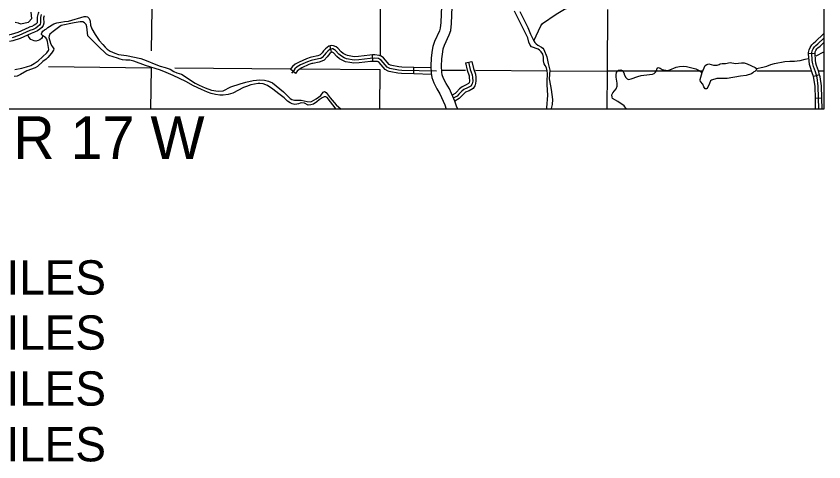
# Model space of a CAD drawing. Extents: x 1373862 to 1376999, y 1168398 to 1170455.
# Drawn here: x 1375806.5 to 1376182.8, y 1168398.5 to 1168606.3 of the extents above; entities that cross this region are included whole.
import ezdxf

# ---------------------------------------------------------------- set-up
doc = ezdxf.new("R2010")
doc.units = 0
for name, color, linetype in [('Level 10', 7, 'Continuous'), ('Level 32', 7, 'Continuous'), ('Level 35', 7, 'Continuous'), ('Level 45', 7, 'Continuous'), ('Level 5', 7, 'Continuous'), ('R_Draft', 7, 'Continuous')]:
    doc.layers.add(name, color=color, linetype=linetype)

msp = doc.modelspace()

# ---------------------------------------------------------------- linework, layer by layer
at = {"layer": 'Level 10'}
for points in [[(1376004.64, 1168610.93), (1376004.32, 1168603.27), (1376004.04, 1168600.69), (1376003.62, 1168599.45), (1376001.3, 1168594.52), (1376000.59, 1168592.17), (1376000.25, 1168590.43), (1375999.83, 1168586.77), (1375999.7, 1168582.99), (1375999.84, 1168579.72), (1376000.12, 1168577.72), (1376001.01, 1168575.19), (1376002.44, 1168572.4), (1376003.84, 1168570.04), (1376006.15, 1168564.87), (1376006.74, 1168562.99)], [(1376012.17, 1168562.99), (1376011.58, 1168564.28), (1376010.83, 1168566.65), (1376008.29, 1168572.34), (1376006.82, 1168574.82), (1376005.61, 1168577.17), (1376005, 1168578.9), (1376004.82, 1168580.17), (1376004.7, 1168583.01), (1376004.82, 1168586.39), (1376005.19, 1168589.66), (1376005.45, 1168590.97), (1376005.98, 1168592.72), (1376008.27, 1168597.58), (1376008.96, 1168599.63), (1376009.3, 1168602.9), (1376009.64, 1168610.64)]]:
    msp.add_lwpolyline(points, dxfattribs=at)
at = {"layer": 'Level 32'}
for p, q in [((1376182.76, 1168597.59), (1376182.47, 1168597.89)), ((1376178.67, 1168588.83), (1376175.67, 1168588.67)), ((1376180.76, 1168578.89), (1376177.87, 1168578.07)), ((1376181.8, 1168568.05), (1376178.8, 1168567.96))]:
    msp.add_line(p, q, dxfattribs=at)
for points in [[(1376175.67, 1168588.67), (1376175.64, 1168589.26), (1376175.92, 1168590.54), (1376176.38, 1168591.67), (1376177.12, 1168592.87), (1376177.96, 1168593.74), (1376179.03, 1168594.57), (1376182.47, 1168597.89)], [(1376180.47, 1168562.99), (1376180.16, 1168573.6), (1376179.58, 1168577.67), (1376178.81, 1168580.37), (1376177.94, 1168582.78), (1376177.62, 1168583.98), (1376177.37, 1168585.54), (1376177.18, 1168589.14), (1376177.38, 1168590.08), (1376177.75, 1168590.97), (1376178.33, 1168591.93), (1376178.98, 1168592.6), (1376180.03, 1168593.42), (1376182.76, 1168596.05)], [(1376182.47, 1168597.89), (1376182.56, 1168597.98), (1376182.76, 1168598.24)], [(1376178.67, 1168588.83), (1376178.66, 1168589.02), (1376178.79, 1168589.64), (1376179.06, 1168590.3), (1376179.5, 1168591.02), (1376179.97, 1168591.5), (1376181, 1168592.31), (1376182.76, 1168594)], [(1376177.87, 1168578.07), (1376177.36, 1168579.9), (1376176.48, 1168582.32), (1376176.12, 1168583.67), (1376175.85, 1168585.38), (1376175.67, 1168588.67)], [(1376180.76, 1168578.89), (1376180.22, 1168580.82), (1376179.34, 1168583.22), (1376179.06, 1168584.29), (1376178.84, 1168585.7), (1376178.67, 1168588.83)], [(1376178.8, 1168567.96), (1376178.64, 1168573.47), (1376178.08, 1168577.35), (1376177.87, 1168578.07)], [(1376181.8, 1168568.05), (1376181.63, 1168573.73), (1376181.02, 1168577.97), (1376180.76, 1168578.89)], [(1376178.94, 1168562.99), (1376178.8, 1168567.96)], [(1376181.95, 1168562.99), (1376181.8, 1168568.05)]]:
    msp.add_lwpolyline(points, dxfattribs=at)
at = {"layer": 'Level 35'}
for points in [[(1376047.64, 1168594.74), (1376050.83, 1168601.79), (1376051.65, 1168602.88), (1376058.05, 1168607.27), (1376061.92, 1168609.53), (1376064.44, 1168610.39), (1376066.44, 1168610.78), (1376072.96, 1168610.95), (1376075.51, 1168611.11), (1376076.3, 1168611.03), (1376080.45, 1168610.95)], [(1375805.8, 1168581.38), (1375809.04, 1168582.07), (1375811.22, 1168582.65), (1375813.31, 1168583.32), (1375814.85, 1168584.17), (1375816.78, 1168585.5), (1375820.7, 1168589.1), (1375821.54, 1168590.23), (1375821.65, 1168590.71), (1375821.11, 1168594.42), (1375820.75, 1168595.48), (1375820.34, 1168596.17), (1375818.69, 1168597.22), (1375818.33, 1168597.71), (1375818.24, 1168598.03), (1375818.39, 1168598.57), (1375818.86, 1168599.26), (1375819.61, 1168599.83), (1375820.52, 1168600.29), (1375821.28, 1168601.04), (1375823.94, 1168602.7), (1375825.43, 1168603.21), (1375827.24, 1168603.54), (1375829.03, 1168603.81), (1375830.92, 1168603.94), (1375838.15, 1168606.08), (1375839.05, 1168606.07), (1375839.71, 1168605.92), (1375840.48, 1168605.12), (1375840.92, 1168603.96), (1375841.11, 1168602.13), (1375841.72, 1168600.42), (1375843.22, 1168597.65), (1375845.2, 1168594.92), (1375846.78, 1168593.13)], [(1375812.21, 1168603.46), (1375813.81, 1168605.26), (1375813.51, 1168608.06)], [(1376053.56, 1168562.99), (1376053.76, 1168563.47), (1376054.12, 1168569.39), (1376053.86, 1168574.24), (1376053.83, 1168575.88), (1376053.97, 1168579.5), (1376053.91, 1168580.74), (1376053.49, 1168582.23), (1376052.95, 1168583.34), (1376052.48, 1168584.03), (1376052.12, 1168585.4), (1376052.15, 1168587.14), (1376051.77, 1168588.48), (1376051.03, 1168589.66), (1376050.32, 1168590.41), (1376049.6, 1168590.88), (1376046.57, 1168592.03), (1376045.98, 1168592.72), (1376045.36, 1168594.19), (1376044.89, 1168596.24), (1376038.58, 1168608.54)], [(1376041.11, 1168608.49), (1376044.79, 1168601.03), (1376046.09, 1168597.86), (1376047.64, 1168594.74), (1376048.15, 1168593.99), (1376048.76, 1168593.38), (1376049.57, 1168592.74), (1376051.22, 1168591.8), (1376051.76, 1168591.39), (1376052.27, 1168590.78), (1376053.74, 1168587.25), (1376054.29, 1168584.16), (1376054.99, 1168581.77), (1376055.04, 1168581.03), (1376054.85, 1168577.13), (1376054.9, 1168576.28), (1376055.73, 1168572.03), (1376056.35, 1168567.35), (1376056.18, 1168565.08), (1376055.78, 1168563.16), (1376055.71, 1168562.99)], [(1375833.5, 1168603.12), (1375827.42, 1168601.86), (1375823.68, 1168599.14), (1375822.17, 1168597.86), (1375821.78, 1168597.17), (1375821.74, 1168596.33), (1375822.5, 1168593.61), (1375822.97, 1168592.59), (1375823.44, 1168591.96), (1375823.96, 1168591.03), (1375823.91, 1168590.37), (1375822.91, 1168589.02), (1375821.25, 1168587.07), (1375820.45, 1168586.28), (1375818.91, 1168585.11), (1375816.38, 1168582.73), (1375815.34, 1168582.16), (1375811.47, 1168580.75), (1375808.55, 1168579.01), (1375806.95, 1168578.3), (1375805.58, 1168578.16)], [(1375805.99, 1168603.55), (1375807.37, 1168603.18), (1375808.48, 1168602.64)], [(1375808.48, 1168602.64), (1375812.21, 1168603.46)], [(1375955.55, 1168562.99), (1375953.92, 1168564.88), (1375952.88, 1168566.38), (1375951.37, 1168568.29), (1375950.75, 1168568.68), (1375949.93, 1168568.63), (1375949.08, 1168568.21), (1375947.7, 1168567.33), (1375946.5, 1168566.31), (1375945.03, 1168565.29), (1375943.76, 1168564.87), (1375942.48, 1168564.83), (1375940.79, 1168565.7), (1375939.48, 1168565.92), (1375938.78, 1168565.76), (1375938.03, 1168565.43), (1375937.29, 1168565.24), (1375936.22, 1168565.16), (1375935, 1168565.44), (1375934.04, 1168565.83), (1375932.93, 1168566.61), (1375931.29, 1168568.12), (1375928.91, 1168570.02), (1375926.08, 1168572.17), (1375923.5, 1168573.89), (1375921.49, 1168574.69), (1375919.98, 1168574.89), (1375919.28, 1168574.86), (1375915.86, 1168574.2), (1375913.72, 1168573.53), (1375912.4, 1168572.98), (1375907.36, 1168570.38), (1375905.2, 1168569.71), (1375902.95, 1168569.43), (1375901.3, 1168569.46), (1375899.34, 1168569.73), (1375897.38, 1168570.28), (1375895.53, 1168570.91), (1375892.84, 1168572.02), (1375889.09, 1168573.8), (1375885.45, 1168575.76), (1375879.58, 1168578.64), (1375876.37, 1168580.02), (1375873.78, 1168581.02), (1375866.67, 1168583.28), (1375861.34, 1168585.27), (1375859.44, 1168585.7), (1375857.62, 1168585.75), (1375855.95, 1168585.94), (1375854.89, 1168586.19), (1375853.62, 1168586.72), (1375849.56, 1168587.86), (1375848.59, 1168588.6), (1375844.48, 1168592.39), (1375839.92, 1168597.11), (1375839.37, 1168601.32), (1375839.07, 1168602.35), (1375838.36, 1168603.2), (1375837.56, 1168603.61), (1375836.34, 1168603.69), (1375833.5, 1168603.12)], [(1375818.69, 1168597.22), (1375818.51, 1168596.26), (1375818.28, 1168595.85), (1375817.51, 1168595.16), (1375816.74, 1168594.87), (1375815.61, 1168594.65), (1375814.83, 1168594.8), (1375813.32, 1168595.39), (1375812.33, 1168596.46), (1375812.06, 1168597.19), (1375812.01, 1168597.54)], [(1375846.78, 1168593.13), (1375847.98, 1168591.75), (1375848.83, 1168590.96), (1375850.2, 1168589.99), (1375852.39, 1168588.98), (1375854.09, 1168588.47), (1375857.81, 1168587.95), (1375864.53, 1168586.46), (1375867.05, 1168585.61), (1375871.55, 1168583.66), (1375873.53, 1168582.96), (1375875.81, 1168582.41), (1375878.28, 1168581.56), (1375879.95, 1168580.5), (1375881.35, 1168579.85), (1375883.54, 1168579.2), (1375889.86, 1168575.11), (1375891.69, 1168574.1), (1375894.5, 1168572.83), (1375897.53, 1168571.84), (1375900.51, 1168571.35), (1375902.96, 1168571.49), (1375906.51, 1168573.29), (1375910.89, 1168574.78), (1375913.41, 1168575.5), (1375916.94, 1168576.28), (1375920.03, 1168576.61), (1375922.2, 1168576.42), (1375923.96, 1168575.93), (1375925.81, 1168575.18), (1375930.96, 1168570.97), (1375934.1, 1168567.89), (1375934.93, 1168567.38), (1375936.17, 1168567.04), (1375938.26, 1168567.16), (1375939.3, 1168567.09), (1375942.06, 1168566.42), (1375943.45, 1168566.32), (1375944.13, 1168566.53), (1375946.28, 1168567.71), (1375948.39, 1168569.36), (1375949.48, 1168570.9), (1375950.17, 1168571.13), (1375950.88, 1168570.64), (1375952.75, 1168568.15), (1375955.55, 1168564.96), (1375957.95, 1168562.99)], [(1376179.15, 1168587.83), (1376182.76, 1168589.71)], [(1376126.06, 1168580.07), (1376127.44, 1168583.29), (1376128.17, 1168583.72), (1376129.12, 1168584), (1376131.28, 1168583.41), (1376133.06, 1168583.46), (1376133.97, 1168583.76), (1376134.48, 1168584.04), (1376135.45, 1168584.28), (1376136.91, 1168584.26), (1376139.11, 1168584.68), (1376141.67, 1168584.28), (1376144.44, 1168584.59), (1376145.59, 1168584.59), (1376147.08, 1168584.05), (1376150.77, 1168582.34), (1376151.4, 1168581.89), (1376151.44, 1168581.63), (1376151.19, 1168581.08), (1376150.66, 1168580.51), (1376150.17, 1168580.25), (1376149.6, 1168579.78), (1376149.03, 1168579.45), (1376146.63, 1168578.61), (1376143.94, 1168578.34), (1376137.68, 1168577.28), (1376132.92, 1168577.14), (1376130.38, 1168576.5), (1376129.95, 1168576.08), (1376129.53, 1168574.81), (1376128.38, 1168572.59), (1376128.1, 1168572.43), (1376127.46, 1168572.32), (1376126.87, 1168573.31), (1376126.35, 1168574.5), (1376125.31, 1168575.76), (1376125.1, 1168576.44), (1376125.06, 1168576.73), (1376126.06, 1168580.07)], [(1376151.4, 1168581.89), (1376154.3, 1168582.47), (1376156.24, 1168583.02), (1376158.1, 1168583.76), (1376159.81, 1168584.26), (1376164.52, 1168585.08), (1376166.88, 1168585.34), (1376169.07, 1168585.32), (1376170.33, 1168585.42), (1376171.8, 1168585.64), (1376174.06, 1168586.28), (1376175.47, 1168586.5)], [(1376090.84, 1168562.99), (1376089.67, 1168564.4), (1376086.81, 1168566.47), (1376084.35, 1168567.91), (1376084.07, 1168568.48), (1376084.03, 1168569.56), (1376084.45, 1168570.55), (1376085.97, 1168572.45), (1376086.49, 1168573.64), (1376086.51, 1168575.06), (1376086.02, 1168577.83), (1376086.04, 1168578.93), (1376086.23, 1168579.95), (1376086.65, 1168580.66), (1376087.16, 1168581.13), (1376088.22, 1168581.26), (1376088.9, 1168580.97), (1376089.58, 1168579.87), (1376089.93, 1168578.77), (1376090.43, 1168577.74), (1376091.08, 1168577.01), (1376091.76, 1168576.78), (1376092.97, 1168577), (1376096.08, 1168578.17), (1376097.59, 1168578.6), (1376098.9, 1168578.84), (1376102.88, 1168579.29), (1376103.63, 1168579.52), (1376104.28, 1168580.17), (1376104.78, 1168580.94), (1376105.18, 1168582), (1376105.56, 1168582.33), (1376106.5, 1168582), (1376107.5, 1168581.46)], [(1376107.5, 1168581.46), (1376109.88, 1168580.92), (1376111.07, 1168581.28), (1376113.98, 1168582.47), (1376115.51, 1168582.81), (1376117.18, 1168582.94), (1376118.78, 1168582.85), (1376123.14, 1168581.7), (1376124.41, 1168581.1), (1376126.06, 1168580.07)]]:
    msp.add_lwpolyline(points, dxfattribs=at)
at = {"layer": 'Level 45'}
for p, q in [((1375953.41, 1168589.47), (1375952.8, 1168592.41)), ((1375972.6, 1168585.17), (1375972.52, 1168588.17)), ((1376015.8, 1168584.47), (1376018.72, 1168585.15)), ((1375936.53, 1168579.6), (1375934.3, 1168581.6)), ((1375991.71, 1168579.35), (1375991.78, 1168582.35))]:
    msp.add_line(p, q, dxfattribs=at)
for points in [[(1375818.11, 1168607.02), (1375817.74, 1168605.62), (1375817.84, 1168603.18), (1375817.69, 1168602.52), (1375817.34, 1168602.06), (1375816.61, 1168601.4), (1375815.59, 1168600.69), (1375814.38, 1168600.11), (1375812.85, 1168599.6), (1375807.73, 1168597.26), (1375804.56, 1168596.21)], [(1375816.98, 1168608.1), (1375816.7, 1168607.65), (1375816.2, 1168605.79), (1375816.3, 1168603.32), (1375816.27, 1168603.18), (1375816.21, 1168603.09), (1375815.66, 1168602.6), (1375814.81, 1168602.01), (1375813.81, 1168601.53), (1375812.44, 1168601.07)], [(1375819.52, 1168606.49), (1375819.48, 1168606.43), (1375819.22, 1168605.46), (1375819.32, 1168603.05), (1375819.06, 1168601.89), (1375818.43, 1168601.05), (1375817.53, 1168600.25), (1375816.33, 1168599.41), (1375814.93, 1168598.74), (1375813.38, 1168598.23)], [(1375812.44, 1168601.07), (1375812.3, 1168601.03), (1375807.17, 1168598.68), (1375804.2, 1168597.7), (1375802.82, 1168597.48)], [(1375813.39, 1168598.23), (1375808.27, 1168595.89), (1375804.91, 1168594.77), (1375803.29, 1168594.51)], [(1376002.3, 1168580.57), (1375986.07, 1168580.96), (1375984.52, 1168581.11), (1375980.6, 1168581.9), (1375980.3, 1168581.98), (1375979.29, 1168582.56), (1375976.57, 1168585.72), (1375975.8, 1168586.26), (1375975.26, 1168586.51), (1375973.58, 1168586.67), (1375971.35, 1168586.61), (1375966.16, 1168585.94), (1375963.91, 1168585.83), (1375960.38, 1168586.39), (1375959.29, 1168586.85), (1375957.97, 1168587.65), (1375956.83, 1168588.57), (1375955.27, 1168590.24), (1375954.77, 1168590.61), (1375953.96, 1168590.98), (1375953.61, 1168591.01), (1375952.77, 1168590.84), (1375951.67, 1168589.96), (1375950.81, 1168589.09), (1375950.16, 1168588.18), (1375949.07, 1168586.96), (1375948.34, 1168586.61), (1375947.35, 1168586.33), (1375943.87, 1168585.6), (1375942.25, 1168585.03), (1375938.94, 1168583.52), (1375937.4, 1168582.63), (1375936.3, 1168581.69), (1375935.82, 1168581.01), (1375934.7, 1168579.77)], [(1375952.8, 1168592.41), (1375952.1, 1168592.26), (1375950.65, 1168591.1), (1375949.63, 1168590.07), (1375948.97, 1168589.13), (1375948.14, 1168588.21), (1375947.8, 1168588.04), (1375946.98, 1168587.82), (1375944.11, 1168587.21)], [(1375962.31, 1168587.63), (1375960.8, 1168587.87), (1375959.99, 1168588.21), (1375958.85, 1168588.9), (1375957.88, 1168589.69), (1375956.29, 1168591.39), (1375955.55, 1168591.94), (1375954.36, 1168592.48), (1375953.52, 1168592.56), (1375952.8, 1168592.41)], [(1375944.11, 1168587.21), (1375943.46, 1168587.07), (1375941.68, 1168586.45), (1375938.24, 1168584.88), (1375936.52, 1168583.89), (1375935.17, 1168582.73), (1375934.62, 1168581.96), (1375934.3, 1168581.6)], [(1375953.41, 1168589.47), (1375952.66, 1168588.87), (1375951.94, 1168588.14), (1375951.32, 1168587.26), (1375949.97, 1168585.76), (1375948.86, 1168585.23), (1375947.7, 1168584.9), (1375944.74, 1168584.27)], [(1375961.84, 1168584.67), (1375959.97, 1168584.96), (1375958.62, 1168585.54), (1375957.12, 1168586.44), (1375955.83, 1168587.49), (1375954.29, 1168589.14), (1375954.02, 1168589.34), (1375953.63, 1168589.51), (1375953.41, 1168589.47)], [(1375972.52, 1168588.17), (1375971.24, 1168588.13), (1375966.03, 1168587.47), (1375964, 1168587.36), (1375962.31, 1168587.63)], [(1375981.56, 1168583.27), (1375980.94, 1168583.4), (1375980.88, 1168583.41), (1375980.28, 1168583.76), (1375977.61, 1168586.85), (1375976.57, 1168587.59), (1375975.66, 1168588.01), (1375973.63, 1168588.2), (1375972.52, 1168588.17)], [(1375944.74, 1168584.27), (1375944.27, 1168584.17), (1375942.8, 1168583.66), (1375939.62, 1168582.21), (1375938.26, 1168581.42), (1375937.4, 1168580.69), (1375936.97, 1168580.08), (1375936.53, 1168579.6)], [(1375972.6, 1168585.17), (1375971.47, 1168585.14), (1375966.3, 1168584.48), (1375963.84, 1168584.35), (1375961.84, 1168584.67)], [(1375980.97, 1168580.33), (1375980.27, 1168580.47), (1375979.74, 1168580.6), (1375978.34, 1168581.41), (1375975.57, 1168584.62), (1375975.06, 1168584.98), (1375974.87, 1168585.07), (1375973.54, 1168585.19), (1375972.6, 1168585.17)], [(1375991.78, 1168582.35), (1375986.17, 1168582.48), (1375984.75, 1168582.62), (1375981.56, 1168583.27)], [(1376017.26, 1168584.81), (1376018.05, 1168581.43), (1376018.95, 1168578.85), (1376019.06, 1168577.72), (1376019.17, 1168576.03), (1376018.95, 1168574.68), (1376018.27, 1168573.67), (1376016.81, 1168572.88), (1376015.01, 1168572.09), (1376014.11, 1168571.3), (1376012.76, 1168569.84), (1376011.98, 1168569.05), (1376010.42, 1168568.16)], [(1376015.8, 1168584.47), (1376016.61, 1168581.02), (1376017.47, 1168578.52), (1376017.57, 1168577.6), (1376017.67, 1168576.11), (1376017.52, 1168575.24)], [(1376018.72, 1168585.15), (1376019.49, 1168581.85), (1376020.42, 1168579.17), (1376020.56, 1168577.84), (1376020.68, 1168575.96), (1376020.38, 1168574.12), (1376020.11, 1168573.72)], [(1375991.71, 1168579.35), (1375985.98, 1168579.49), (1375984.3, 1168579.65), (1375980.97, 1168580.33)], [(1375999.67, 1168582.16), (1375991.78, 1168582.35)], [(1375999.92, 1168579.15), (1375991.71, 1168579.35)], [(1376017.52, 1168575.24), (1376017.23, 1168574.81), (1376016.15, 1168574.23), (1376014.2, 1168573.37), (1376013.06, 1168572.38), (1376011.68, 1168570.88), (1376011.06, 1168570.25), (1376009.54, 1168569.39)], [(1376020.11, 1168573.72), (1376019.32, 1168572.52), (1376017.47, 1168571.53), (1376015.83, 1168570.81), (1376015.16, 1168570.23), (1376013.85, 1168568.8), (1376012.9, 1168567.85), (1376010.76, 1168566.62)]]:
    msp.add_lwpolyline(points, dxfattribs=at)
at = {"layer": 'Level 5'}
for points in [[(1375870.45, 1168658.52), (1375869.42, 1168590.17)], [(1375976.13, 1168588.04), (1375976.22, 1168616.97)], [(1376082, 1168609.4), (1376081.81, 1168580.7), (1376081.62, 1168562.99)], [(1375821.45, 1168582.8), (1375869.28, 1168582.23)], [(1375869.3, 1168582.07), (1375869.02, 1168562.99)], [(1375880.4, 1168582.13), (1375934.32, 1168581.68)], [(1375938.92, 1168581.64), (1375976.1, 1168581.33)], [(1375975.91, 1168562.99), (1375976.1, 1168581.33)], [(1376004.94, 1168581.16), (1376015.81, 1168581.09)], [(1376020.53, 1168581.06), (1376053.86, 1168580.86)], [(1376055.22, 1168580.86), (1376081.81, 1168580.7)], [(1376126.01, 1168580.67), (1376081.81, 1168580.7)], [(1376176.68, 1168580.64), (1376151.59, 1168580.66)], [(1376182.76, 1168580.64), (1376180.22, 1168580.64)]]:
    msp.add_lwpolyline(points, dxfattribs=at)
at = {"layer": 'R_Draft'}
msp.add_lwpolyline([(1374675.34, 1169579.43), (1376182.76, 1169579.43), (1376182.76, 1168562.99), (1374675.34, 1168562.99)], close=True, dxfattribs=at)

# ---------------------------------------------------------------- texts
for s, height, p in [('R 17 W', 20, (1375805.09, 1168539.63)), ('MILES', 16, (1375784.1, 1168476.46)), ('MILES', 16, (1375784.1, 1168450.77)), ('MILES', 16, (1375784.1, 1168424.68)), ('MILES', 16, (1375784.1, 1168398.7))]:
    msp.add_text(s, height=height, dxfattribs=at).set_placement(p)

doc.saveas('drawing.dxf')
